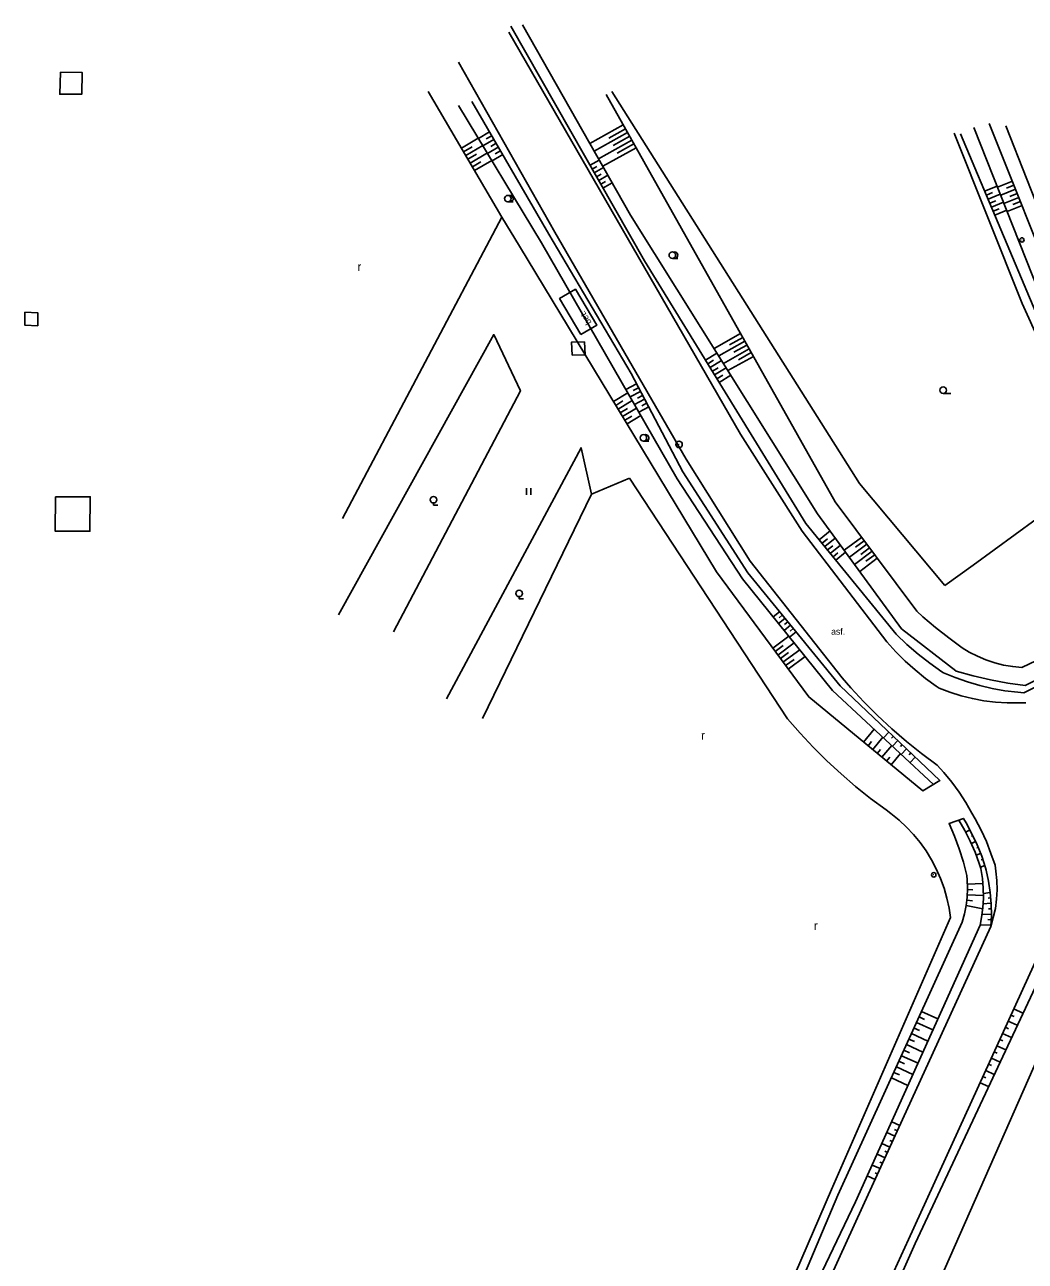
# Model space of a CAD drawing. Extents: x -582162 to -561283, y -1187583 to -1183539.
# Drawn here: x -562958.8 to -562844, y -1186702 to -1186560.1 of the extents above; entities that cross this region are included whole.
import ezdxf

# ---------------------------------------------------------------- set-up
doc = ezdxf.new("R2010")
doc.units = 0
for name, color, linetype in [('Vrstva 1', 7, 'Continuous'), ('Vrstva 10', 7, 'Continuous'), ('Vrstva 11', 7, 'Continuous'), ('Vrstva 12', 7, 'Continuous'), ('Vrstva 14', 7, 'Continuous'), ('Vrstva 3', 7, 'Continuous'), ('Vrstva 9', 7, 'Continuous')]:
    doc.layers.add(name, color=color, linetype=linetype)

# ---------------------------------------------------------------- blocks, each defined once
blk = doc.blocks.new('1.079')
at = {"layer": 'Vrstva 1'}
for radius in [0.75, 0.001]:
    blk.add_circle((0, -0.001), radius, dxfattribs=at)
blk = doc.blocks.new('3.019')
at = {"layer": 'Vrstva 1'}
blk.add_text('r', height=2, dxfattribs=at).set_placement((-0.496, -0.964))
blk = doc.blocks.new('3.040')
at = {"layer": 'Vrstva 1'}
blk.add_line((0, -0.75), (1.75, -0.75), dxfattribs=at)
blk.add_circle((0, 0), 0.75, dxfattribs=at)
blk = doc.blocks.new('3.050')
at = {"layer": 'Vrstva 1'}
blk.add_lwpolyline([(0, -0.75), (0, -1.25), (1, -1.25)], dxfattribs=at)
blk.add_circle((0, 0), 0.75, dxfattribs=at)
blk = doc.blocks.new('3.060')
at = {"layer": 'Vrstva 1'}
for p, q in [((-0.5, -0.75), (-0.5, 0.75)), ((0.5, -0.75), (0.5, 0.75))]:
    blk.add_line(p, q, dxfattribs=at)
blk = doc.blocks.new('3.110')
at = {"layer": 'Vrstva 1'}
blk.add_line((0, -0.75), (1.25, -0.75), dxfattribs=at)
blk.add_circle((0, 0), 0.75, dxfattribs=at)
blk.add_arc((0.5, 0), 0.75, 249.4944, 109.0474, dxfattribs=at)
blk = doc.blocks.new('4.110')
at = {"layer": 'Vrstva 1'}
for radius in [0.5, 0.001]:
    blk.add_circle((-0.001, 0), radius, dxfattribs=at)

msp = doc.modelspace()

# ---------------------------------------------------------------- linework, layer by layer
at = {"layer": 'Vrstva 10'}
for points in [[(-562869.63, -1186618.24), (-562876.71, -1186607.11), (-562903.27, -1186560.95)], [(-562875.59, -1186621.69), (-562882.94, -1186609.96), (-562898.01, -1186583.93), (-562909.06, -1186564.41)], [(-562895.03, -1186595.67), (-562893.2, -1186594.59), (-562895.63, -1186590.47), (-562897.46, -1186591.54), (-562895.03, -1186595.67)], [(-562843.99, -1186637.92), (-562844.77, -1186637.95), (-562846.11, -1186637.94), (-562847.45, -1186637.85), (-562848.78, -1186637.69), (-562850.1, -1186637.44), (-562851.4, -1186637.11), (-562852.68, -1186636.71), (-562853.93, -1186636.23), (-562854.24, -1186636.02), (-562855.49, -1186635.12), (-562856.68, -1186634.16), (-562857.82, -1186633.14), (-562858.9, -1186632.06), (-562859.93, -1186630.92), (-562869.63, -1186618.24)], [(-562847.98, -1186663.6), (-562847.47, -1186661.52), (-562847.33, -1186660.46), (-562847.28, -1186659.4), (-562847.3, -1186658.33), (-562847.4, -1186657.26), (-562847.51, -1186656.58), (-562847.97, -1186655.21), (-562848.5, -1186653.86), (-562849.1, -1186652.54), (-562849.78, -1186651.26), (-562850.16, -1186650.61), (-562850.86, -1186649.38), (-562851.63, -1186648.18), (-562852.47, -1186647.04), (-562853.37, -1186645.94), (-562854.15, -1186645.08), (-562855.93, -1186643.75), (-562857.66, -1186642.36), (-562859.34, -1186640.91), (-562860.97, -1186639.4), (-562862.54, -1186637.83), (-562864.05, -1186636.2), (-562865.06, -1186635.05), (-562875.59, -1186621.69)], [(-562831.75, -1186642.68), (-562833.2, -1186645.98), (-562842.3, -1186666.35), (-562857.44, -1186699.54), (-562865.85, -1186717.9), (-562874.79, -1186737.38), (-562884.24, -1186757.92), (-562893.59, -1186777.96), (-562902.73, -1186797.35), (-562905.06, -1186802.36)], [(-562871.22, -1186714.48), (-562862.66, -1186695.7), (-562847.98, -1186663.6)]]:
    msp.add_lwpolyline(points, dxfattribs=at)
at = {"layer": 'Vrstva 11'}
for points in [[(-562904.08, -1186582.2), (-562922.34, -1186616.77)], [(-562922.81, -1186627.83), (-562905, -1186595.67), (-562901.94, -1186602.13), (-562916.51, -1186629.79)], [(-562910.43, -1186637.46), (-562894.98, -1186608.65), (-562893.78, -1186614)], [(-562893.78, -1186614), (-562889.45, -1186612.15)], [(-562889.45, -1186612.15), (-562871.31, -1186639.75), (-562869.86, -1186641.42), (-562868.36, -1186643.03), (-562866.79, -1186644.59), (-562865.17, -1186646.09), (-562863.5, -1186647.54), (-562861.78, -1186648.92), (-562860, -1186650.23), (-562859.44, -1186650.63), (-562858.52, -1186651.38), (-562857.66, -1186652.19), (-562856.85, -1186653.05), (-562856.1, -1186653.97), (-562855.41, -1186654.93), (-562854.79, -1186655.94), (-562854.24, -1186656.99), (-562853.76, -1186658.08), (-562853.36, -1186659.19), (-562853.03, -1186660.33), (-562852.78, -1186661.49), (-562852.62, -1186662.56)], [(-562893.78, -1186614), (-562906.28, -1186639.73)], [(-562852.62, -1186662.56), (-562866.25, -1186693.8), (-562874.54, -1186712.91), (-562883.61, -1186733.16), (-562892.65, -1186753.11), (-562901.86, -1186773.87), (-562906.32, -1186782.35), (-562906.57, -1186782.64), (-562906.87, -1186782.88), (-562907.22, -1186783.05), (-562907.59, -1186783.14), (-562907.97, -1186783.16), (-562908.24, -1186783.12), (-562909.83, -1186782.6), (-562911.39, -1186782), (-562912.29, -1186781.61), (-562917.09, -1186778.39), (-562928.16, -1186768.97), (-562945.95, -1186752.34), (-562954.48, -1186744.53)]]:
    msp.add_lwpolyline(points, dxfattribs=at)
at = {"layer": 'Vrstva 12'}
for points in [[(-562869.2, -1186617.34), (-562887.71, -1186587.21), (-562903.05, -1186560.29)], [(-562901.69, -1186560.11), (-562889.33, -1186581.95), (-562867.86, -1186616.23)], [(-562912.52, -1186567.76), (-562904.08, -1186582.2)], [(-562907.51, -1186568.93), (-562898.68, -1186584.15)], [(-562865.84, -1186614.88), (-562892.1, -1186568.12)], [(-562876.48, -1186623.71), (-562883.96, -1186612.21), (-562899.51, -1186585.15), (-562909.04, -1186569.37)], [(-562890.15, -1186571.6), (-562893.97, -1186573.75)], [(-562849.93, -1186571.91), (-562841.71, -1186592.67), (-562835.89, -1186605.05), (-562829.25, -1186618.88)], [(-562829.25, -1186618.88), (-562827.91, -1186617.45), (-562834.4, -1186604.39), (-562840.11, -1186591.64), (-562848.17, -1186571.44)], [(-562908.72, -1186574.26), (-562906.78, -1186573.12)], [(-562905.48, -1186572.42), (-562906.75, -1186573.16)], [(-562904.98, -1186573.29), (-562906.24, -1186574.01)], [(-562905.23, -1186572.86), (-562905.86, -1186573.22)], [(-562889.66, -1186572.47), (-562893.48, -1186574.62)], [(-562889.17, -1186573.34), (-562892.99, -1186575.49)], [(-562889.9, -1186572.04), (-562891.81, -1186573.11)], [(-562889.41, -1186572.91), (-562891.32, -1186573.98)], [(-562829.25, -1186618.88), (-562830.16, -1186619.65), (-562836.67, -1186605.67), (-562842.84, -1186593.12), (-562851.47, -1186572.64)], [(-562908.47, -1186574.69), (-562907.49, -1186574.12)], [(-562908.22, -1186575.12), (-562906.26, -1186573.98)], [(-562904.48, -1186574.15), (-562905.72, -1186574.87)], [(-562904.73, -1186573.72), (-562905.35, -1186574.08)], [(-562904.23, -1186574.59), (-562904.84, -1186574.94)], [(-562888.68, -1186574.22), (-562892.49, -1186576.36)], [(-562888.92, -1186573.78), (-562890.83, -1186574.85)], [(-562907.97, -1186575.55), (-562906.98, -1186574.98)], [(-562907.71, -1186575.98), (-562905.74, -1186574.83)], [(-562907.46, -1186576.42), (-562906.47, -1186575.84)], [(-562907.21, -1186576.85), (-562905.23, -1186575.69)], [(-562903.98, -1186575.02), (-562905.2, -1186575.73)], [(-562893.96, -1186576.24), (-562892.9, -1186575.64)], [(-562893.71, -1186576.68), (-562893.18, -1186576.38)], [(-562893.47, -1186577.11), (-562892.41, -1186576.51)], [(-562893.22, -1186577.55), (-562892.69, -1186577.25)], [(-562892.97, -1186577.98), (-562891.92, -1186577.38)], [(-562892.72, -1186578.41), (-562892.2, -1186578.11)], [(-562892.48, -1186578.85), (-562891.42, -1186578.25)], [(-562848.7, -1186579.22), (-562847.27, -1186578.62)], [(-562845.52, -1186578.08), (-562847.22, -1186578.75)], [(-562845.15, -1186579), (-562846.85, -1186579.68)], [(-562845.34, -1186578.54), (-562846.19, -1186578.88)], [(-562848.5, -1186579.68), (-562847.8, -1186579.38)], [(-562848.31, -1186580.14), (-562846.91, -1186579.55)], [(-562848.12, -1186580.6), (-562847.42, -1186580.31)], [(-562844.78, -1186579.93), (-562846.48, -1186580.61)], [(-562844.97, -1186579.47), (-562845.82, -1186579.81)], [(-562844.6, -1186580.4), (-562845.45, -1186580.74)], [(-562847.92, -1186581.06), (-562846.54, -1186580.48)], [(-562847.73, -1186581.52), (-562847.04, -1186581.23)], [(-562847.53, -1186581.98), (-562846.17, -1186581.41)], [(-562844.41, -1186580.86), (-562846.12, -1186581.54)], [(-562904.08, -1186582.2), (-562902.07, -1186585.51), (-562879.44, -1186622.9)], [(-562876.69, -1186595.56), (-562879.74, -1186597.27)], [(-562876.45, -1186595.99), (-562877.96, -1186596.84)], [(-562876.2, -1186596.43), (-562879.2, -1186598.12)], [(-562875.71, -1186597.3), (-562878.67, -1186598.97)], [(-562875.96, -1186596.87), (-562877.45, -1186597.7)], [(-562880.72, -1186598.6), (-562879.41, -1186597.79)], [(-562880.45, -1186599.02), (-562879.8, -1186598.62)], [(-562880.19, -1186599.45), (-562878.88, -1186598.64)], [(-562875.22, -1186598.17), (-562878.14, -1186599.81)], [(-562875.47, -1186597.74), (-562876.94, -1186598.56)], [(-562889.26, -1186600.13), (-562883.31, -1186611.44), (-562875.86, -1186623.03)], [(-562879.93, -1186599.87), (-562879.27, -1186599.47)], [(-562879.67, -1186600.3), (-562878.35, -1186599.49)], [(-562879.41, -1186600.73), (-562878.74, -1186600.32)], [(-562888.63, -1186601.33), (-562889.85, -1186601.97)], [(-562879.15, -1186601.15), (-562877.81, -1186600.34)], [(-562891.27, -1186603.36), (-562889.62, -1186602.36)], [(-562888.17, -1186602.21), (-562889.35, -1186602.83)], [(-562888.4, -1186601.77), (-562889, -1186602.08)], [(-562887.7, -1186603.1), (-562888.85, -1186603.7)], [(-562887.93, -1186602.65), (-562888.52, -1186602.96)], [(-562891.01, -1186603.79), (-562890.19, -1186603.29)], [(-562890.75, -1186604.22), (-562889.12, -1186603.23)], [(-562890.49, -1186604.65), (-562889.68, -1186604.16)], [(-562890.23, -1186605.07), (-562888.62, -1186604.1)], [(-562887.23, -1186603.98), (-562888.35, -1186604.57)], [(-562887.47, -1186603.54), (-562888.03, -1186603.84)], [(-562889.97, -1186605.5), (-562889.17, -1186605.02)], [(-562889.71, -1186605.93), (-562888.12, -1186604.97)], [(-562835.95, -1186629.83), (-562844.43, -1186633.87), (-562845.48, -1186633.77), (-562846.52, -1186633.59), (-562847.54, -1186633.33), (-562848.55, -1186633), (-562849.52, -1186632.59), (-562850.46, -1186632.11), (-562851.26, -1186631.62), (-562852.81, -1186630.49), (-562854.32, -1186629.3), (-562855.77, -1186628.05), (-562856.48, -1186627.4), (-562865.84, -1186614.88)], [(-562869.2, -1186617.34), (-562858.86, -1186630.07), (-562857.62, -1186631.24), (-562856.33, -1186632.34), (-562854.98, -1186633.38), (-562853.59, -1186634.36), (-562853.43, -1186634.47), (-562852.07, -1186635.04), (-562850.68, -1186635.53), (-562849.26, -1186635.94), (-562847.83, -1186636.28), (-562846.38, -1186636.54), (-562844.91, -1186636.72), (-562844.2, -1186636.78), (-562834.59, -1186632.03)], [(-562836.09, -1186631.92), (-562844.04, -1186635.96), (-562846.04, -1186635.66), (-562848.03, -1186635.28), (-562850, -1186634.82), (-562851.95, -1186634.28), (-562852.01, -1186634.26), (-562858.23, -1186629.43), (-562867.86, -1186616.23)], [(-562867.67, -1186619.23), (-562866.42, -1186618.21)], [(-562867.35, -1186619.61), (-562866.74, -1186619.11)], [(-562867.04, -1186620), (-562865.83, -1186619.02)], [(-562866.72, -1186620.39), (-562866.13, -1186619.91)], [(-562866.41, -1186620.78), (-562865.24, -1186619.83)], [(-562862.81, -1186618.94), (-562864.8, -1186620.43)], [(-562862.21, -1186619.74), (-562864.21, -1186621.23)], [(-562862.51, -1186619.34), (-562863.51, -1186620.08)], [(-562861.91, -1186620.14), (-562862.91, -1186620.89)], [(-562866.09, -1186621.17), (-562865.52, -1186620.7)], [(-562865.78, -1186621.56), (-562864.65, -1186620.64)], [(-562861.61, -1186620.54), (-562863.62, -1186622.04)], [(-562861.01, -1186621.34), (-562863.03, -1186622.85)], [(-562861.31, -1186620.94), (-562862.32, -1186621.69)], [(-562879.44, -1186622.9), (-562868.88, -1186637.26), (-562855.8, -1186648.03), (-562853.83, -1186646.83), (-562865.28, -1186635.97), (-562875.86, -1186623.03)], [(-562876.48, -1186623.71), (-562866.14, -1186636.51), (-562854.58, -1186647.29)], [(-562872.23, -1186627.47), (-562872.96, -1186628.07)], [(-562871.6, -1186628.24), (-562872.33, -1186628.84)], [(-562871.91, -1186627.86), (-562872.28, -1186628.16)], [(-562871.28, -1186628.63), (-562871.65, -1186628.93)], [(-562870.97, -1186629.02), (-562871.7, -1186629.62)], [(-562870.33, -1186629.79), (-562871.08, -1186630.4)], [(-562870.65, -1186629.4), (-562871.02, -1186629.71)], [(-562873.01, -1186631.64), (-562871.17, -1186630.28)], [(-562872.72, -1186632.04), (-562871.79, -1186631.36)], [(-562872.42, -1186632.45), (-562870.54, -1186631.06)], [(-562872.12, -1186632.85), (-562871.18, -1186632.15)], [(-562871.83, -1186633.25), (-562869.91, -1186631.84)], [(-562871.53, -1186633.65), (-562870.56, -1186632.94)], [(-562871.24, -1186634.06), (-562869.28, -1186632.62)], [(-562862.6, -1186642.43), (-562861.38, -1186640.95)], [(-562859.67, -1186641.3), (-562860.3, -1186641.96)], [(-562862.07, -1186642.87), (-562861.67, -1186642.38)], [(-562861.54, -1186643.3), (-562860.37, -1186641.89)], [(-562860.48, -1186644.18), (-562859.36, -1186642.83)], [(-562859.16, -1186641.77), (-562859.37, -1186641.99)], [(-562858.66, -1186642.25), (-562859.28, -1186642.9)], [(-562858.16, -1186642.72), (-562858.36, -1186642.94)], [(-562861.01, -1186643.74), (-562860.63, -1186643.28)], [(-562859.95, -1186644.62), (-562859.58, -1186644.18)], [(-562859.42, -1186645.05), (-562858.36, -1186643.76)], [(-562857.66, -1186643.2), (-562858.27, -1186643.85)], [(-562857.15, -1186643.68), (-562857.36, -1186643.89)], [(-562856.65, -1186644.15), (-562857.26, -1186644.79)], [(-562851.27, -1186663.11), (-562851, -1186662.16), (-562850.8, -1186661.2), (-562850.73, -1186660.59), (-562850.69, -1186660.22), (-562850.65, -1186659.24), (-562850.69, -1186658.25), (-562850.75, -1186657.73), (-562851.14, -1186656.21), (-562851.61, -1186654.7), (-562852.16, -1186653.23), (-562852.78, -1186651.78), (-562851.13, -1186651.19), (-562850.83, -1186651.7), (-562850.16, -1186652.95), (-562849.56, -1186654.23), (-562849.04, -1186655.54), (-562848.59, -1186656.88), (-562848.53, -1186657.13), (-562848.26, -1186658.41), (-562848.07, -1186659.7), (-562847.96, -1186661), (-562847.93, -1186662.3), (-562847.98, -1186663.6)], [(-562851.66, -1186651.38), (-562850.97, -1186652.57), (-562850.35, -1186653.81), (-562849.8, -1186655.07), (-562849.32, -1186656.37), (-562849.13, -1186656.96), (-562848.96, -1186658.08), (-562848.86, -1186659.2), (-562848.84, -1186660.33), (-562848.91, -1186661.46), (-562849.05, -1186662.58), (-562849.22, -1186663.45)], [(-562850.39, -1186652.52), (-562850.86, -1186652.77)], [(-562849.74, -1186653.85), (-562850.22, -1186654.07)], [(-562850.05, -1186653.18), (-562850.21, -1186653.25)], [(-562849.17, -1186655.21), (-562849.66, -1186655.41)], [(-562849.44, -1186654.52), (-562849.61, -1186654.59)], [(-562848.68, -1186656.61), (-562849.19, -1186656.78)], [(-562848.92, -1186655.91), (-562849.08, -1186655.96)], [(-562850.67, -1186658.76), (-562848.89, -1186658.68)], [(-562850.66, -1186659.37), (-562850.05, -1186659.39)], [(-562848.07, -1186659.7), (-562848.84, -1186659.8)], [(-562850.8, -1186661.2), (-562848.92, -1186661.58)], [(-562850.73, -1186660.59), (-562850.11, -1186660.67)], [(-562850.68, -1186659.98), (-562848.84, -1186660.05)], [(-562847.97, -1186660.94), (-562848.87, -1186661.01)], [(-562848.02, -1186660.31), (-562848.29, -1186660.33)], [(-562847.93, -1186662.19), (-562849, -1186662.22)], [(-562847.95, -1186661.56), (-562848.27, -1186661.57)], [(-562847.97, -1186663.45), (-562849.21, -1186663.4)], [(-562847.95, -1186662.82), (-562848.33, -1186662.81)], [(-562856.22, -1186673.98), (-562855.59, -1186674.27)], [(-562855.93, -1186673.35), (-562854.05, -1186674.2)], [(-562845.68, -1186673.76), (-562845.33, -1186673.92)], [(-562845.36, -1186673.05), (-562844.3, -1186673.54)], [(-562856.8, -1186675.25), (-562856.17, -1186675.54)], [(-562856.51, -1186674.62), (-562854.63, -1186675.47)], [(-562846.32, -1186675.17), (-562845.98, -1186675.33)], [(-562846, -1186674.46), (-562844.95, -1186674.94)], [(-562857.38, -1186676.52), (-562856.75, -1186676.81)], [(-562857.09, -1186675.89), (-562855.2, -1186676.75)], [(-562846.97, -1186676.58), (-562846.63, -1186676.74)], [(-562846.65, -1186675.88), (-562845.61, -1186676.35)], [(-562857.95, -1186677.8), (-562857.32, -1186678.08)], [(-562857.67, -1186677.16), (-562855.77, -1186678.02)], [(-562847.61, -1186678), (-562847.27, -1186678.15)], [(-562847.29, -1186677.29), (-562846.27, -1186677.75)], [(-562858.82, -1186679.7), (-562856.92, -1186680.57)], [(-562858.53, -1186679.07), (-562857.9, -1186679.36)], [(-562858.24, -1186678.43), (-562856.34, -1186679.3)], [(-562848.26, -1186679.41), (-562847.92, -1186679.56)], [(-562847.93, -1186678.7), (-562846.93, -1186679.16)], [(-562859.4, -1186680.97), (-562857.49, -1186681.84)], [(-562859.11, -1186680.34), (-562858.48, -1186680.63)], [(-562848.9, -1186680.82), (-562848.57, -1186680.97)], [(-562848.58, -1186680.11), (-562847.59, -1186680.57)], [(-562849.22, -1186681.53), (-562848.25, -1186681.97)], [(-562858.42, -1186686.43), (-562859.36, -1186686)], [(-562858.99, -1186687.67), (-562859.92, -1186687.25)], [(-562859.27, -1186688.29), (-562859.58, -1186688.15)], [(-562858.7, -1186687.05), (-562859.02, -1186686.91)], [(-562860.12, -1186690.15), (-562861.04, -1186689.73)], [(-562859.56, -1186688.91), (-562860.48, -1186688.49)], [(-562859.84, -1186689.53), (-562860.15, -1186689.39)], [(-562860.69, -1186691.39), (-562861.6, -1186690.98)], [(-562860.41, -1186690.77), (-562860.71, -1186690.63)], [(-562861.26, -1186692.63), (-562862.16, -1186692.22)], [(-562860.97, -1186692.01), (-562861.27, -1186691.87)]]:
    msp.add_lwpolyline(points, dxfattribs=at)
at = {"layer": 'Vrstva 9'}
for points in [[(-562954.71, -1186565.55), (-562954.79, -1186568.08), (-562952.27, -1186568.09), (-562952.21, -1186565.61), (-562954.71, -1186565.55)], [(-562891.45, -1186567.78), (-562863.04, -1186612.77)], [(-562839.04, -1186590.09), (-562846.27, -1186571.73)], [(-562844.4, -1186592.1), (-562852.21, -1186572.57)], [(-562889.26, -1186600.13), (-562898.68, -1186584.15)], [(-562958.78, -1186593.08), (-562958.8, -1186594.58), (-562957.3, -1186594.66), (-562957.28, -1186593.18), (-562958.78, -1186593.08)], [(-562850, -1186622.13), (-562835.57, -1186611.58), (-562844.4, -1186592.1)], [(-562894.61, -1186596.49), (-562896.07, -1186596.53), (-562896.01, -1186598.02), (-562894.51, -1186597.99), (-562894.61, -1186596.49)], [(-562863.04, -1186612.77), (-562853.25, -1186624.46)], [(-562955.28, -1186614.28), (-562951.28, -1186614.29), (-562951.33, -1186618.24), (-562955.32, -1186618.23), (-562955.28, -1186614.28)], [(-562853.25, -1186624.46), (-562850, -1186622.13)], [(-562902.04, -1186805.4), (-562900.55, -1186798.41), (-562892.08, -1186778.74), (-562883.03, -1186758.61), (-562873.58, -1186737.81), (-562864.86, -1186718.39), (-562856.67, -1186699.97), (-562841.16, -1186666.84), (-562831.91, -1186647.61)], [(-562829.65, -1186647.93), (-562832.47, -1186657.31), (-562838, -1186668.28), (-562853.17, -1186702.7), (-562861.43, -1186720.83), (-562870.74, -1186739.36), (-562881.44, -1186762.43), (-562890.35, -1186779.52), (-562899.66, -1186798.85), (-562902.04, -1186805.4)], [(-562891.15, -1186754.04), (-562891.44, -1186753.57), (-562882.5, -1186733.5), (-562873.49, -1186713.3), (-562865.53, -1186694.44), (-562851.27, -1186663.11)], [(-562849.22, -1186663.45), (-562863.5, -1186695.21), (-562872.45, -1186713.91), (-562881.61, -1186733.95), (-562891.15, -1186754.04)]]:
    msp.add_lwpolyline(points, dxfattribs=at)

# ---------------------------------------------------------------- block references
at = {"layer": 'Vrstva 1', "xscale": 0.5, "yscale": 0.5, "rotation": 90}
msp.add_blockref('1.079', (-562883.75, -1186608.27), dxfattribs=at)
at = {"layer": 'Vrstva 3', "xscale": 0.5, "yscale": 0.5}
for name, p in [('3.110', (-562903.4, -1186580.07)), ('3.110', (-562884.52, -1186586.55)), ('3.019', (-562920.39, -1186587.9)), ('3.040', (-562853.46, -1186602.05)), ('3.110', (-562887.84, -1186607.53)), ('3.050', (-562911.91, -1186614.62)), ('3.060', (-562901.01, -1186613.68)), ('3.050', (-562902.1, -1186625.37)), ('3.019', (-562880.98, -1186641.68)), ('3.019', (-562868.04, -1186663.53))]:
    msp.add_blockref(name, p, dxfattribs=at)
at = {"layer": 'Vrstva 9', "xscale": 0.5, "yscale": 0.5}
for p in [(-562844.42, -1186584.81), (-562854.53, -1186657.67)]:
    msp.add_blockref('4.110', p, dxfattribs=at)

# ---------------------------------------------------------------- texts
at = {"layer": 'Vrstva 14'}
msp.add_text('bet.', height=0.75, rotation=120.53, dxfattribs=at).set_placement((-562893.76, -1186594.29))
msp.add_text('asf.', height=0.75, dxfattribs=at).set_placement((-562866.31, -1186630.12))

doc.saveas('drawing.dxf')
